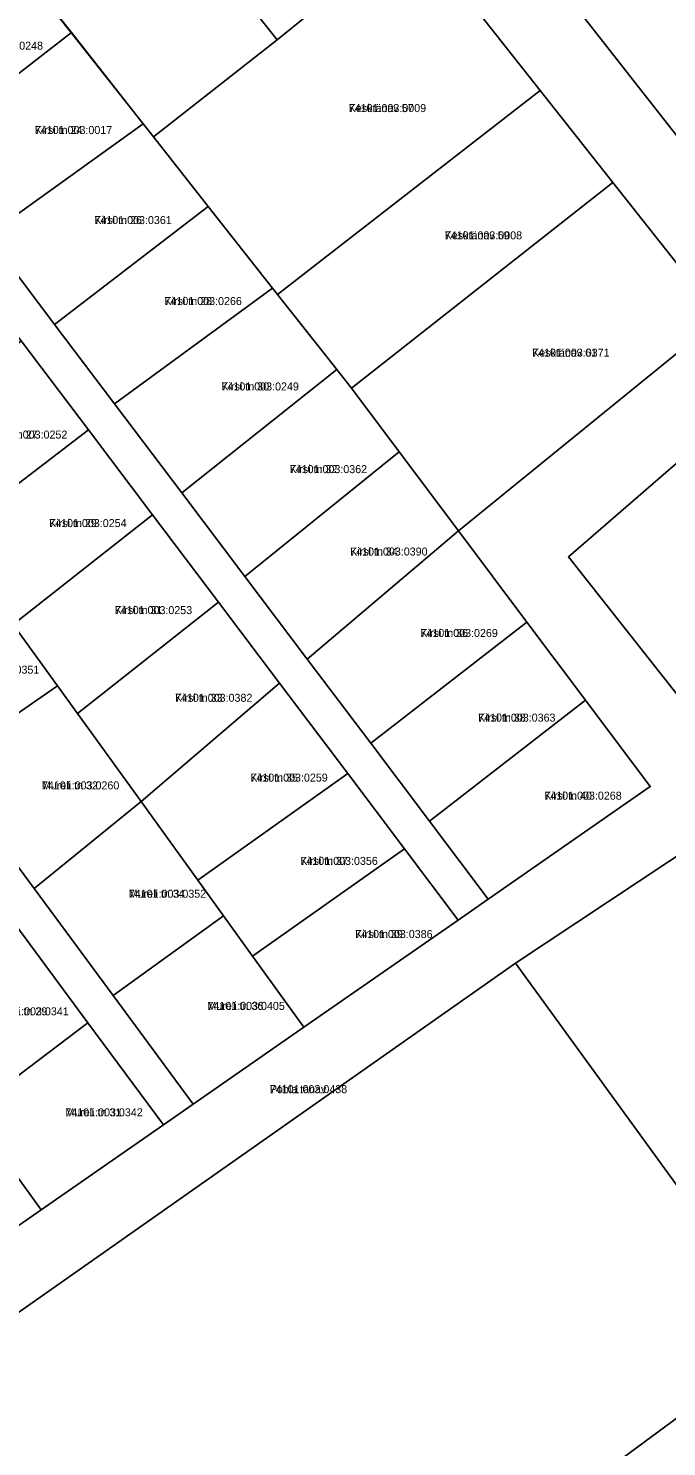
# Model space of a CAD drawing. Extents: x 524000 to 564260, y 6469338 to 6496391.
# Drawn here: x 539055.5 to 539175.1, y 6472943.6 to 6473209.4 of the extents above; entities that cross this region are included whole.
import ezdxf

# ---------------------------------------------------------------- set-up
doc = ezdxf.new("R2010")
doc.units = 0
for name, color, linetype in [('L_AADRESS', 7, 'Continuous'), ('PIIR', 7, 'Continuous'), ('TUNNUS', 7, 'Continuous')]:
    doc.layers.add(name, color=color, linetype=linetype)

msp = doc.modelspace()

# ---------------------------------------------------------------- linework, layer by layer
at = {"layer": 'PIIR'}
for points in [[(539153.84, 6473218.89), (539195.05, 6473247.44), (539196.73, 6473248.61), (539180.59, 6473269.14), (539275.2, 6473343.45), (539312.81, 6473297.15), (539400.31, 6473189.4), (539301.24, 6473114.3), (539268.62, 6473155.84), (539227.91, 6473124.34)], [(539093.3, 6473218.4), (539102.07, 6473207.27), (539078.93, 6473189.06), (539057.52, 6473216.25), (539080.1, 6473235.18)], [(539101.24, 6473160.73), (539089.19, 6473176.03), (539078.93, 6473189.06), (539102.07, 6473207.27), (539127.62, 6473227.91), (539151.41, 6473197.77), (539102.19, 6473159.52)], [(539023.95, 6473202.18), (539051.45, 6473223.95), (539057.52, 6473216.25), (539063.53, 6473208.62), (539035.51, 6473186.87)], [(539035.51, 6473186.87), (539063.53, 6473208.62), (539077, 6473191.51), (539047.8, 6473170.57)], [(539113.29, 6473145.45), (539102.19, 6473159.52), (539151.41, 6473197.77), (539165.04, 6473180.5), (539116.04, 6473141.95)], [(539047.8, 6473170.57), (539077, 6473191.51), (539078.93, 6473189.06), (539089.19, 6473176.03), (539060.37, 6473153.93)], [(539185.12, 6473155.08), (539136.07, 6473115.23), (539124.98, 6473130.03), (539116.04, 6473141.95), (539165.04, 6473180.5)], [(539101.24, 6473160.73), (539071.58, 6473139.06), (539060.37, 6473153.93), (539089.19, 6473176.03)], [(539102.19, 6473159.52), (539113.29, 6473145.45), (539084.21, 6473122.34), (539071.58, 6473139.06), (539101.24, 6473160.73)], [(539031.73, 6473126.64), (539029.16, 6473130.2), (539054.12, 6473150.83), (539066.71, 6473134.16), (539040.71, 6473114.21)], [(539116.04, 6473141.95), (539124.98, 6473130.03), (539096.06, 6473106.64), (539084.21, 6473122.34), (539113.29, 6473145.45)], [(539194.49, 6473143.12), (539217.42, 6473114.08), (539178.19, 6473083.11), (539156.68, 6473110.35)], [(539078.72, 6473118.23), (539052.64, 6473097.69), (539046.92, 6473105.61), (539040.71, 6473114.21), (539066.71, 6473134.16)], [(539124.98, 6473130.03), (539136.07, 6473115.23), (539107.74, 6473091.17), (539096.06, 6473106.64)], [(539091.08, 6473101.86), (539064.68, 6473081.01), (539060.94, 6473086.2), (539052.64, 6473097.69), (539078.72, 6473118.23)], [(539148.9, 6473098.13), (539119.63, 6473075.42), (539107.74, 6473091.17), (539136.07, 6473115.23)], [(539052.64, 6473097.69), (539060.94, 6473086.2), (539039.43, 6473071.3), (539025.23, 6473090.48), (539046.92, 6473105.61)], [(539091.08, 6473101.86), (539102.54, 6473086.67), (539076.59, 6473064.51), (539064.68, 6473081.01)], [(539159.88, 6473083.49), (539130.65, 6473060.81), (539119.63, 6473075.42), (539148.9, 6473098.13)], [(539236.07, 6473090.55), (539291.55, 6473020.27), (539197.65, 6472964.18), (539146.78, 6473034.18), (539192.75, 6473064.71), (539196.82, 6473059.57)], [(539064.68, 6473081.01), (539076.59, 6473064.51), (539056.55, 6473048.18), (539039.43, 6473071.3), (539060.94, 6473086.2)], [(539076.59, 6473064.51), (539102.54, 6473086.67), (539115.33, 6473069.73), (539087.23, 6473049.79)], [(539172.02, 6473067.3), (539141.67, 6473046.21), (539130.65, 6473060.81), (539159.88, 6473083.49)], [(539125.97, 6473055.63), (539097.47, 6473035.51), (539092.07, 6473043.08), (539087.23, 6473049.79), (539115.33, 6473069.73)], [(539056.55, 6473048.18), (539076.59, 6473064.51), (539087.23, 6473049.79), (539092.03, 6473043.09), (539071.33, 6473028.16)], [(539125.97, 6473055.63), (539136.04, 6473042.29), (539107.07, 6473022.19), (539097.47, 6473035.51)], [(539092.03, 6473043.09), (539097.47, 6473035.51), (539107.07, 6473022.19), (539086.37, 6473007.8), (539071.33, 6473028.16)], [(539044.06, 6473007.02), (539031.12, 6473024.87), (539052.24, 6473042.5), (539066.63, 6473023.05), (539044.55, 6473006.35)], [(538943.24, 6472891.21), (539146.78, 6473034.18), (539197.65, 6472964.18), (538996.48, 6472815.75)], [(539044.55, 6473006.35), (539066.63, 6473023.05), (539080.81, 6473003.9), (539057.88, 6472987.95)], [(539022.79, 6472989.23), (539044.06, 6473007.02), (539044.55, 6473006.35), (539057.88, 6472987.95), (539035.14, 6472972.15)]]:
    msp.add_lwpolyline(points, close=True, dxfattribs=at)
for points in [[(539153.84, 6473218.89), (539227.91, 6473124.34), (539223.54, 6473120.96), (539256.06, 6473079.57), (539299.51, 6473025.88), (539291.55, 6473020.27), (539236.07, 6473090.55), (539217.42, 6473114.08), (539194.49, 6473143.12), (539185.12, 6473155.08), (539165.04, 6473180.5), (539151.41, 6473197.77), (539127.62, 6473227.91), (539102.07, 6473207.27), (539093.3, 6473218.4)], [(538935.8, 6473211.27), (538950.43, 6473191.51), (538964.27, 6473172.81), (538979.53, 6473152.19), (538995.37, 6473130.8), (539009.9, 6473111.19), (539025.23, 6473090.48), (539039.43, 6473071.3), (539056.55, 6473048.18), (539071.33, 6473028.16), (539086.37, 6473007.8), (539080.81, 6473003.9), (539066.63, 6473023.05), (539052.24, 6473042.5), (539037.32, 6473062.65), (539022.81, 6473082.24), (539007.52, 6473102.91), (538989.88, 6473126.73), (538975.47, 6473146.18), (538957.74, 6473170.12), (538939.08, 6473195.34), (538920.87, 6473219.93)], [(539011.51, 6473218.66), (539023.95, 6473202.18), (539035.51, 6473186.87), (539047.8, 6473170.57), (539060.37, 6473153.93), (539071.58, 6473139.06), (539084.21, 6473122.34), (539096.06, 6473106.64), (539107.74, 6473091.17), (539119.63, 6473075.42), (539130.65, 6473060.81), (539141.67, 6473046.21), (539136.04, 6473042.29), (539125.97, 6473055.63), (539115.33, 6473069.73), (539102.54, 6473086.67), (539091.08, 6473101.86), (539078.72, 6473118.23), (539066.71, 6473134.16), (539054.12, 6473150.83), (539042.59, 6473166.11), (539029.89, 6473182.94), (539018.84, 6473197.57), (539005.75, 6473214.93)], [(539192.75, 6473064.71), (539146.78, 6473034.18), (538943.24, 6472891.21), (538904.95, 6472864.61), (538897.02, 6472876.14), (538908.25, 6472883.95), (538935.88, 6472903.16), (538968.64, 6472925.93), (538974.26, 6472929.84), (539004.27, 6472950.7), (539029.6, 6472968.3), (539035.14, 6472972.15), (539057.88, 6472987.95), (539080.81, 6473003.9), (539086.37, 6473007.8), (539107.07, 6473022.19), (539136.04, 6473042.29), (539141.67, 6473046.21), (539172.02, 6473067.3), (539159.88, 6473083.49), (539148.9, 6473098.13), (539136.07, 6473115.23), (539185.12, 6473155.08)], [(539194.49, 6473143.12), (539156.68, 6473110.35), (539178.19, 6473083.11)]]:
    msp.add_lwpolyline(points, dxfattribs=at)

# ---------------------------------------------------------------- texts
at = {"layer": 'L_AADRESS'}
for s, p in [('Kesktänav 57', (539115.52, 6473193.71)), ('Kirsi tn 24', (539056.68, 6473189.6)), ('Kirsi tn 26', (539067.84, 6473172.72)), ('Kesktänav 59', (539133.51, 6473169.86)), ('Kirsi tn 28', (539080.98, 6473157.54)), ('Kesktänav 61', (539149.9, 6473147.87)), ('Kirsi tn 30', (539091.67, 6473141.54)), ('Kirsi tn 27', (539048.27, 6473132.52)), ('Kirsi tn 32', (539104.46, 6473126.04)), ('Kirsi tn 29', (539059.37, 6473115.93)), ('Kirsi tn 34', (539115.79, 6473110.6)), ('Kirsi tn 31', (539071.67, 6473099.62)), ('Kirsi tn 36', (539128.96, 6473095.33)), ('Kirsi tn 33', (539082.95, 6473083.19)), ('Kirsi tn 38', (539139.77, 6473079.47)), ('Kirsi tn 35', (539097.08, 6473068.23)), ('Mureli tn 32', (539058.01, 6473066.77)), ('Kirsi tn 40', (539152.18, 6473064.85)), ('Kirsi tn 37', (539106.46, 6473052.62)), ('Mureli tn 34', (539074.29, 6473046.47)), ('Kirsi tn 39', (539116.73, 6473038.91)), ('Mureli tn 29', (539048.53, 6473024.43)), ('Mureli tn 36', (539089.03, 6473025.45)), ('Pohla tänav', (539100.72, 6473009.84)), ('Mureli tn 31', (539062.4, 6473005.5))]:
    msp.add_text(s, height=1.5, dxfattribs=at).set_placement(p)
at = {"layer": 'TUNNUS'}
for s, p in [('74101:003:0248', (539043.71, 6473205.41)), ('74101:003:0009', (539115.52, 6473193.71)), ('74101:003:0017', (539056.68, 6473189.6)), ('74101:003:0361', (539067.84, 6473172.72)), ('74101:003:0008', (539133.51, 6473169.86)), ('74101:003:0266', (539080.98, 6473157.54)), ('74101:003:0371', (539149.9, 6473147.87)), ('74101:003:0249', (539091.67, 6473141.54)), ('74101:003:0252', (539048.27, 6473132.52)), ('74101:003:0362', (539104.46, 6473126.04)), ('74101:003:0254', (539059.37, 6473115.93)), ('74101:003:0390', (539115.79, 6473110.6)), ('74101:003:0253', (539071.67, 6473099.62)), ('74101:003:0269', (539128.96, 6473095.33)), ('74101:003:0351', (539043.02, 6473088.46)), ('74101:003:0382', (539082.95, 6473083.19)), ('74101:003:0363', (539139.77, 6473079.47)), ('74101:003:0259', (539097.08, 6473068.23)), ('74101:003:0260', (539058.01, 6473066.77)), ('74101:003:0268', (539152.18, 6473064.85)), ('74101:003:0356', (539106.46, 6473052.62)), ('74101:003:0352', (539074.29, 6473046.47)), ('74101:003:0386', (539116.73, 6473038.91)), ('74101:003:0341', (539048.53, 6473024.43)), ('74101:003:0405', (539089.03, 6473025.45)), ('74101:003:0438', (539100.72, 6473009.84)), ('74101:003:0342', (539062.4, 6473005.5))]:
    msp.add_text(s, height=1.5, dxfattribs=at).set_placement(p)

doc.saveas('drawing.dxf')
